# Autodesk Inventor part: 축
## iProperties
Created: 2015-03
Part Number: 축
Material: Steel
Document SubType Name: Modeling
Designer: KYOUNG IL JANG
Density: 1 g/cm^3
CustomPartVersion: 1
Author: KYOUNG IL JANG
